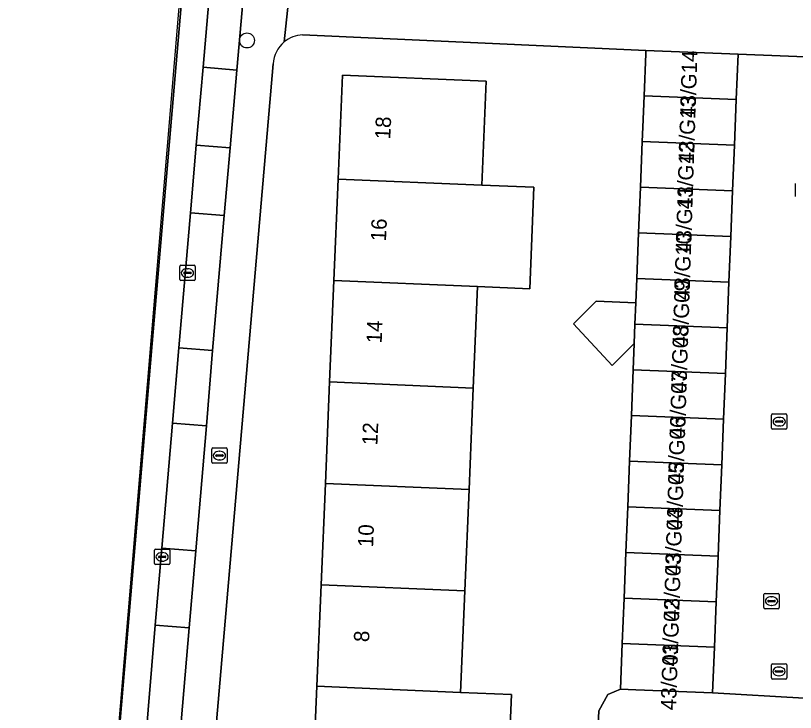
# Model space of a CAD drawing. Extents: x 161354 to 162026, y 386504 to 387460.
# Drawn here: x 161385.3 to 161436.1, y 386908.4 to 386953.7 of the extents above; entities that cross this region are included whole.
import ezdxf

# ---------------------------------------------------------------- set-up
doc = ezdxf.new("R2010")
doc.units = 0
for name, color, linetype in [('IMGEO_Boom', 7, 'Continuous'), ('IMGEO_Brandkraan', 7, 'Continuous'), ('IMGEO_Erf', 7, 'Continuous'), ('IMGEO_Kolk', 7, 'Continuous'), ('IMGEO_Pand', 7, 'Continuous'), ('IMGEO_Pand_nummerreeks', 7, 'Continuous'), ('IMGEO_Parkeervlak_open', 7, 'Continuous'), ('IMGEO_Rijbaan_lokaal_gesloten', 7, 'Continuous'), ('IMGEO_Rijbaan_lokaal_open', 7, 'Continuous'), ('IMGEO_Rioolput', 7, 'Continuous'), ('IMGEO_Voetpad_open', 7, 'Continuous')]:
    doc.layers.add(name, color=color, linetype=linetype)

msp = doc.modelspace()

# ---------------------------------------------------------------- linework, layer by layer
at = {"layer": 'IMGEO_Boom'}
msp.add_circle((161400.403, 386952.127), 0.489, dxfattribs=at)
at = {"layer": 'IMGEO_Brandkraan'}
for p, q in [((161398.112, 386924.666), (161398.112, 386925.518)), ((161398.187, 386925.592), (161399.039, 386925.592)), ((161399.113, 386925.518), (161399.113, 386924.666)), ((161398.371, 386925.086), (161398.371, 386925.098)), ((161398.809, 386925.049), (161398.411, 386925.049)), ((161398.414, 386925.135), (161398.812, 386925.135)), ((161398.6, 386925.372), (161398.625, 386925.372)), ((161398.855, 386925.098), (161398.855, 386925.086)), ((161399.039, 386924.592), (161398.187, 386924.592)), ((161398.623, 386924.812), (161398.598, 386924.812))]:
    msp.add_line(p, q, dxfattribs=at)
for points in [[(161398.112, 386924.666), (161398.112, 386925.518)], [(161398.187, 386925.592), (161399.039, 386925.592)], [(161399.113, 386925.518), (161399.113, 386924.666)], [(161399.039, 386924.592), (161398.187, 386924.592)]]:
    msp.add_lwpolyline(points, dxfattribs=at)
for centre, radius, start, end in [((161398.189, 386925.516), 0.0765, 91.552, 178.448), ((161398.189, 386925.516), 0.0765, 91.552, 178.448), ((161399.037, 386925.516), 0.0765, 1.552, 88.448), ((161399.037, 386925.516), 0.0765, 1.552, 88.448), ((161398.411, 386925.095), 0.0403, 85.8775, 175.7526), ((161398.408, 386925.085), 0.0366, 178.938, 274.7102), ((161398.812, 386925.092), 0.043, 264.8664, 352.4533), ((161398.816, 386925.097), 0.0386, 1.7309, 96.639), ((161398.189, 386924.668), 0.0765, 181.552, 268.448), ((161398.189, 386924.668), 0.0765, 181.552, 268.448), ((161399.037, 386924.668), 0.0765, 271.552, 358.448), ((161399.037, 386924.668), 0.0765, 271.552, 358.448)]:
    msp.add_arc(centre, radius, start, end, dxfattribs=at)
for centre, major_axis, ratio, start_param, end_param in [((161398.599, 386925.092), (-0.387, 0.002), 0.722429, 4.712389, 7.853982), ((161398.624, 386925.092), (-0.39, 0.002), 0.717154, 1.570796, 4.712389)]:
    msp.add_ellipse(centre, major_axis=major_axis, ratio=ratio, start_param=start_param, end_param=end_param, dxfattribs=at)
at = {"layer": 'IMGEO_Erf'}
for points in [[(161425.091, 386918.792), (161425.209, 386921.764), (161425.327, 386924.736), (161425.445, 386927.707), (161425.563, 386930.679), (161425.631, 386932.394), (161424.203, 386930.958), (161421.671, 386933.664), (161423.142, 386935.143), (161425.736, 386935.04), (161425.799, 386936.623), (161425.917, 386939.595), (161426.035, 386942.567), (161426.153, 386945.539), (161426.191, 386946.487), (161426.271, 386948.51), (161426.38, 386951.257), (161426.389, 386951.483), (161404.023, 386952.492)], [(161402.118, 386950.602), (161396.472, 386885.071)], [(161404.675, 386903.466), (161404.953, 386910.072), (161405.232, 386916.678), (161405.511, 386923.284), (161405.789, 386929.89), (161406.068, 386936.496), (161406.347, 386943.103), (161406.632, 386949.86), (161415.99, 386949.466), (161415.705, 386942.708), (161419.102, 386942.565), (161418.823, 386935.958), (161415.426, 386936.101), (161415.147, 386929.495), (161414.869, 386922.889), (161414.59, 386916.283), (161414.311, 386909.678), (161417.64, 386909.538), (161417.362, 386902.932)], [(161398.199, 386883.13), (161402.57, 386883.034), (161422.037, 386882.246), (161423.317, 386908.469), (161423.916, 386909.531), (161424.737, 386909.876), (161424.855, 386912.848), (161424.973, 386915.82), (161425.091, 386918.792)]]:
    msp.add_lwpolyline(points, dxfattribs=at)
for centre, radius, start, end in [((161404.098, 386950.507), 1.987, 92.1688, 129.8934), ((161404.096, 386950.514), 1.98, 129.9717, 177.4448)]:
    msp.add_arc(centre, radius, start, end, dxfattribs=at)
at = {"layer": 'IMGEO_Kolk'}
for p, q in [((161396.028, 386936.559), (161396.028, 386937.411)), ((161396.103, 386937.485), (161396.955, 386937.485)), ((161396.516, 386937.265), (161396.541, 386937.265)), ((161397.029, 386937.411), (161397.029, 386936.559)), ((161396.287, 386936.979), (161396.287, 386936.991)), ((161396.725, 386936.942), (161396.327, 386936.942)), ((161396.33, 386937.028), (161396.728, 386937.028)), ((161396.539, 386936.705), (161396.514, 386936.705)), ((161396.771, 386936.991), (161396.771, 386936.979)), ((161396.955, 386936.485), (161396.103, 386936.485)), ((161434.574, 386926.879), (161434.574, 386927.731)), ((161434.649, 386927.805), (161435.501, 386927.805)), ((161435.062, 386927.585), (161435.087, 386927.585)), ((161435.575, 386927.731), (161435.575, 386926.879)), ((161434.833, 386927.299), (161434.833, 386927.311)), ((161435.271, 386927.262), (161434.873, 386927.262)), ((161434.876, 386927.348), (161435.274, 386927.348)), ((161435.085, 386927.025), (161435.06, 386927.025)), ((161435.317, 386927.311), (161435.317, 386927.299)), ((161435.501, 386926.805), (161434.649, 386926.805)), ((161394.378, 386918.073), (161394.378, 386918.925)), ((161394.453, 386918.999), (161395.305, 386918.999)), ((161395.379, 386918.925), (161395.379, 386918.073)), ((161394.637, 386918.493), (161394.637, 386918.505)), ((161395.075, 386918.456), (161394.677, 386918.456)), ((161394.68, 386918.542), (161395.078, 386918.542)), ((161394.866, 386918.779), (161394.891, 386918.779)), ((161395.121, 386918.505), (161395.121, 386918.493)), ((161395.305, 386917.999), (161394.453, 386917.999)), ((161394.889, 386918.219), (161394.864, 386918.219)), ((161434.077, 386915.196), (161434.077, 386916.048)), ((161434.152, 386916.122), (161435.004, 386916.122)), ((161434.565, 386915.902), (161434.59, 386915.902)), ((161435.078, 386916.048), (161435.078, 386915.196)), ((161434.336, 386915.616), (161434.336, 386915.628)), ((161434.774, 386915.579), (161434.376, 386915.579)), ((161434.379, 386915.665), (161434.777, 386915.665)), ((161434.588, 386915.342), (161434.563, 386915.342)), ((161434.82, 386915.628), (161434.82, 386915.616)), ((161435.004, 386915.122), (161434.152, 386915.122))]:
    msp.add_line(p, q, dxfattribs=at)
for points in [[(161396.028, 386936.559), (161396.028, 386937.411)], [(161396.103, 386937.485), (161396.955, 386937.485)], [(161397.029, 386937.411), (161397.029, 386936.559)], [(161396.955, 386936.485), (161396.103, 386936.485)], [(161434.574, 386926.879), (161434.574, 386927.731)], [(161434.649, 386927.805), (161435.501, 386927.805)], [(161435.575, 386927.731), (161435.575, 386926.879)], [(161435.501, 386926.805), (161434.649, 386926.805)], [(161394.378, 386918.073), (161394.378, 386918.925)], [(161394.453, 386918.999), (161395.305, 386918.999)], [(161395.379, 386918.925), (161395.379, 386918.073)], [(161395.305, 386917.999), (161394.453, 386917.999)], [(161434.077, 386915.196), (161434.077, 386916.048)], [(161434.152, 386916.122), (161435.004, 386916.122)], [(161435.078, 386916.048), (161435.078, 386915.196)], [(161435.004, 386915.122), (161434.152, 386915.122)]]:
    msp.add_lwpolyline(points, dxfattribs=at)
for centre, radius, start, end in [((161396.105, 386937.409), 0.0765, 91.552, 178.448), ((161396.105, 386937.409), 0.0765, 91.552, 178.448), ((161396.953, 386937.409), 0.0765, 1.552, 88.448), ((161396.953, 386937.409), 0.0765, 1.552, 88.448), ((161396.327, 386936.988), 0.0403, 85.8775, 175.7526), ((161396.324, 386936.978), 0.0366, 178.938, 274.7102), ((161396.728, 386936.985), 0.043, 264.8664, 352.4533), ((161396.732, 386936.99), 0.0386, 1.7309, 96.639), ((161396.105, 386936.561), 0.0765, 181.552, 268.448), ((161396.105, 386936.561), 0.0765, 181.552, 268.448), ((161396.953, 386936.561), 0.0765, 271.552, 358.448), ((161396.953, 386936.561), 0.0765, 271.552, 358.448), ((161434.651, 386927.729), 0.0765, 91.552, 178.448), ((161434.651, 386927.729), 0.0765, 91.552, 178.448), ((161435.499, 386927.729), 0.0765, 1.552, 88.448), ((161435.499, 386927.729), 0.0765, 1.552, 88.448), ((161434.873, 386927.308), 0.0403, 85.8775, 175.7526), ((161434.87, 386927.298), 0.0366, 178.938, 274.7102), ((161435.274, 386927.305), 0.043, 264.8664, 352.4533), ((161435.278, 386927.31), 0.0386, 1.7309, 96.639), ((161434.651, 386926.881), 0.0765, 181.552, 268.448), ((161434.651, 386926.881), 0.0765, 181.552, 268.448), ((161435.499, 386926.881), 0.0765, 271.552, 358.448), ((161435.499, 386926.881), 0.0765, 271.552, 358.448), ((161394.455, 386918.923), 0.0765, 91.552, 178.448), ((161394.455, 386918.923), 0.0765, 91.552, 178.448), ((161395.303, 386918.923), 0.0765, 1.552, 88.448), ((161395.303, 386918.923), 0.0765, 1.552, 88.448), ((161394.677, 386918.502), 0.0403, 85.8775, 175.7526), ((161394.674, 386918.492), 0.0366, 178.938, 274.7102), ((161395.078, 386918.499), 0.043, 264.8664, 352.4533), ((161395.082, 386918.504), 0.0386, 1.7309, 96.639), ((161394.455, 386918.075), 0.0765, 181.552, 268.448), ((161394.455, 386918.075), 0.0765, 181.552, 268.448), ((161395.303, 386918.075), 0.0765, 271.552, 358.448), ((161395.303, 386918.075), 0.0765, 271.552, 358.448), ((161434.154, 386916.046), 0.0765, 91.552, 178.448), ((161434.154, 386916.046), 0.0765, 91.552, 178.448), ((161435.002, 386916.046), 0.0765, 1.552, 88.448), ((161435.002, 386916.046), 0.0765, 1.552, 88.448), ((161434.376, 386915.625), 0.0403, 85.8775, 175.7526), ((161434.373, 386915.615), 0.0366, 178.938, 274.7102), ((161434.777, 386915.622), 0.043, 264.8664, 352.4533), ((161434.781, 386915.627), 0.0386, 1.7309, 96.639), ((161434.154, 386915.198), 0.0765, 181.552, 268.448), ((161434.154, 386915.198), 0.0765, 181.552, 268.448), ((161435.002, 386915.198), 0.0765, 271.552, 358.448), ((161435.002, 386915.198), 0.0765, 271.552, 358.448)]:
    msp.add_arc(centre, radius, start, end, dxfattribs=at)
for centre, major_axis, ratio, start_param, end_param in [((161396.515, 386936.985), (-0.387, 0.002), 0.722429, 4.712389, 7.853982), ((161396.54, 386936.985), (-0.39, 0.002), 0.717154, 1.570796, 4.712389), ((161435.061, 386927.305), (-0.387, 0.002), 0.722429, 4.712389, 7.853982), ((161435.086, 386927.305), (-0.39, 0.002), 0.717154, 1.570796, 4.712389), ((161394.865, 386918.499), (-0.387, 0.002), 0.722429, 4.712389, 7.853982), ((161394.89, 386918.499), (-0.39, 0.002), 0.717154, 1.570796, 4.712389), ((161434.564, 386915.622), (-0.387, 0.002), 0.722429, 4.712389, 7.853982), ((161434.589, 386915.622), (-0.39, 0.002), 0.717154, 1.570796, 4.712389)]:
    msp.add_ellipse(centre, major_axis=major_axis, ratio=ratio, start_param=start_param, end_param=end_param, dxfattribs=at)
at = {"layer": 'IMGEO_Pand'}
for points in [[(161432.392, 386951.244), (161426.389, 386951.483), (161426.38, 386951.257), (161426.271, 386948.51), (161432.274, 386948.272)], [(161415.705, 386942.708), (161415.99, 386949.466), (161406.632, 386949.86), (161406.347, 386943.103)], [(161432.274, 386948.272), (161426.271, 386948.51), (161426.191, 386946.487), (161426.153, 386945.539), (161432.156, 386945.3)], [(161432.156, 386945.3), (161426.153, 386945.539), (161426.035, 386942.567), (161432.038, 386942.328)], [(161418.823, 386935.958), (161419.102, 386942.565), (161415.705, 386942.708), (161406.347, 386943.103), (161406.068, 386936.496), (161415.426, 386936.101)], [(161432.038, 386942.328), (161426.035, 386942.567), (161425.917, 386939.595), (161431.92, 386939.357)], [(161431.92, 386939.357), (161425.917, 386939.595), (161425.799, 386936.623), (161431.802, 386936.385)], [(161415.147, 386929.495), (161415.426, 386936.101), (161406.068, 386936.496), (161405.789, 386929.89)], [(161431.802, 386936.385), (161425.799, 386936.623), (161425.736, 386935.04), (161425.681, 386933.651), (161431.684, 386933.413)], [(161425.681, 386933.651), (161425.736, 386935.04), (161423.142, 386935.143), (161421.671, 386933.664), (161424.203, 386930.958), (161425.631, 386932.394)], [(161431.684, 386933.413), (161425.681, 386933.651), (161425.631, 386932.394), (161425.563, 386930.679), (161431.566, 386930.441)], [(161431.566, 386930.441), (161425.563, 386930.679), (161425.445, 386927.707), (161431.448, 386927.469)], [(161414.869, 386922.889), (161415.147, 386929.495), (161405.789, 386929.89), (161405.511, 386923.284)], [(161431.448, 386927.469), (161425.445, 386927.707), (161425.327, 386924.736), (161431.33, 386924.497)], [(161431.33, 386924.497), (161425.327, 386924.736), (161425.209, 386921.764), (161431.212, 386921.525)], [(161405.511, 386923.284), (161405.232, 386916.678), (161414.59, 386916.283), (161414.869, 386922.889)], [(161431.212, 386921.525), (161425.209, 386921.764), (161425.091, 386918.792), (161431.094, 386918.554)], [(161431.094, 386918.554), (161425.091, 386918.792), (161424.973, 386915.82), (161430.976, 386915.582)], [(161414.311, 386909.678), (161414.59, 386916.283), (161405.232, 386916.678), (161404.953, 386910.072)], [(161430.976, 386915.582), (161424.973, 386915.82), (161424.855, 386912.848), (161430.858, 386912.61)], [(161430.858, 386912.61), (161424.855, 386912.848), (161424.737, 386909.876), (161425.744, 386909.836), (161430.74, 386909.638)], [(161414.311, 386909.678), (161404.953, 386910.072), (161404.675, 386903.466), (161414.033, 386903.072), (161417.362, 386902.932), (161417.64, 386909.538)]]:
    msp.add_lwpolyline(points, close=True, dxfattribs=at)
at = {"layer": 'IMGEO_Parkeervlak_open'}
for points in [[(161401.052, 386964.949), (161398.813, 386965.051), (161397.56, 386950.381), (161399.743, 386950.199)], [(161399.306, 386945.132), (161397.098, 386945.3), (161396.726, 386940.898), (161398.926, 386940.724)], [(161398.169, 386931.948), (161395.968, 386932.108), (161395.562, 386927.216), (161397.759, 386927.033)], [(161397.063, 386918.895), (161394.863, 386919.073), (161394.434, 386914.054), (161396.638, 386913.88)]]:
    msp.add_lwpolyline(points, close=True, dxfattribs=at)
at = {"layer": 'IMGEO_Rijbaan_lokaal_gesloten'}
for points in [[(161407.469, 387085.902), (161407.502, 387088.315), (161407.694, 387090.665), (161407.844, 387092.692), (161407.62, 387092.708), (161403.029, 387038.37), (161389.859, 386881.623), (161385.332, 386827.741)], [(161406.674, 387079.565), (161402.616, 387030.052), (161394.233, 386932.401), (161389.344, 386874.852), (161388.763, 386863.237), (161388.746, 386863.053), (161388.119, 386839.423)], [(161388.119, 386839.423), (161388.746, 386863.053), (161388.763, 386863.237), (161389.344, 386874.852), (161394.233, 386932.401), (161402.616, 387030.052), (161406.674, 387079.565)], [(161393.289, 386900.719), (161393.743, 386905.917), (161394.434, 386914.054), (161394.863, 386919.073), (161395.562, 386927.216), (161395.968, 386932.108), (161396.726, 386940.898), (161397.098, 386945.3), (161397.56, 386950.381), (161398.813, 386965.051), (161399.546, 386973.261), (161399.972, 386978.208), (161400.667, 386986.316), (161401.089, 386991.236), (161401.793, 386999.383), (161402.199, 387004.388), (161402.917, 387012.858), (161403.316, 387017.566), (161403.709, 387022.054)]]:
    msp.add_lwpolyline(points, dxfattribs=at)
at = {"layer": 'IMGEO_Rijbaan_lokaal_open'}
msp.add_lwpolyline([(161441.686, 386950.859), (161432.392, 386951.244), (161432.274, 386948.272), (161432.156, 386945.3), (161432.038, 386942.328), (161431.92, 386939.357), (161431.802, 386936.385), (161431.684, 386933.413), (161431.566, 386930.441), (161431.448, 386927.469), (161431.33, 386924.497), (161431.212, 386921.525), (161431.094, 386918.554), (161430.976, 386915.582), (161430.858, 386912.61), (161430.74, 386909.638), (161436.696, 386909.288)], dxfattribs=at)
for points in [[(161399.743, 386950.199), (161397.56, 386950.381), (161397.098, 386945.3), (161399.306, 386945.132)], [(161398.926, 386940.724), (161396.726, 386940.898), (161395.968, 386932.108), (161398.169, 386931.948)], [(161397.759, 386927.033), (161395.562, 386927.216), (161394.863, 386919.073), (161397.063, 386918.895)], [(161396.638, 386913.88), (161394.434, 386914.054), (161393.743, 386905.917), (161395.938, 386905.726)]]:
    msp.add_lwpolyline(points, close=True, dxfattribs=at)
at = {"layer": 'IMGEO_Rioolput'}
for p, q in [((161436.13, 386941.957), (161436.13, 386942.809)), ((161434.563, 386910.616), (161434.563, 386911.468)), ((161434.638, 386911.542), (161435.49, 386911.542)), ((161435.051, 386911.322), (161435.076, 386911.322)), ((161435.564, 386911.468), (161435.564, 386910.616)), ((161434.822, 386911.036), (161434.822, 386911.048)), ((161435.26, 386910.999), (161434.862, 386910.999)), ((161434.865, 386911.085), (161435.263, 386911.085)), ((161435.074, 386910.762), (161435.049, 386910.762)), ((161435.306, 386911.048), (161435.306, 386911.036)), ((161435.49, 386910.542), (161434.638, 386910.542))]:
    msp.add_line(p, q, dxfattribs=at)
for points in [[(161436.13, 386941.957), (161436.13, 386942.809)], [(161434.563, 386910.616), (161434.563, 386911.468)], [(161434.638, 386911.542), (161435.49, 386911.542)], [(161435.564, 386911.468), (161435.564, 386910.616)], [(161435.49, 386910.542), (161434.638, 386910.542)]]:
    msp.add_lwpolyline(points, dxfattribs=at)
for centre, radius, start, end in [((161434.64, 386911.466), 0.0765, 91.552, 178.448), ((161434.64, 386911.466), 0.0765, 91.552, 178.448), ((161435.488, 386911.466), 0.0765, 1.552, 88.448), ((161435.488, 386911.466), 0.0765, 1.552, 88.448), ((161434.862, 386911.045), 0.0403, 85.8775, 175.7526), ((161434.859, 386911.035), 0.0366, 178.938, 274.7102), ((161435.263, 386911.042), 0.043, 264.8664, 352.4533), ((161435.267, 386911.047), 0.0386, 1.7309, 96.639), ((161434.64, 386910.618), 0.0765, 181.552, 268.448), ((161434.64, 386910.618), 0.0765, 181.552, 268.448), ((161435.488, 386910.618), 0.0765, 271.552, 358.448), ((161435.488, 386910.618), 0.0765, 271.552, 358.448)]:
    msp.add_arc(centre, radius, start, end, dxfattribs=at)
for centre, major_axis, ratio, start_param, end_param in [((161435.05, 386911.042), (-0.387, 0.002), 0.722429, 4.712389, 7.853982), ((161435.075, 386911.042), (-0.39, 0.002), 0.717154, 1.570796, 4.712389)]:
    msp.add_ellipse(centre, major_axis=major_axis, ratio=ratio, start_param=start_param, end_param=end_param, dxfattribs=at)
at = {"layer": 'IMGEO_Voetpad_open'}
for points in [[(161406.704, 387031.106), (161405.921, 387021.886), (161405.516, 387017.383), (161405.133, 387012.676), (161404.391, 387004.207), (161403.992, 386999.21), (161403.265, 386991.063), (161402.872, 386986.156), (161402.159, 386978.009), (161401.738, 386973.087), (161401.052, 386964.949), (161399.743, 386950.199), (161399.306, 386945.132), (161398.926, 386940.724), (161398.169, 386931.948), (161397.759, 386927.033), (161397.063, 386918.895), (161396.638, 386913.88), (161395.938, 386905.726), (161395.517, 386900.935), (161393.823, 386901.064)], [(161403.227, 386955.728), (161402.824, 386952.031)], [(161402.824, 386952.031), (161403.227, 386955.728)], [(161404.023, 386952.492), (161426.389, 386951.483), (161432.392, 386951.244), (161441.686, 386950.859), (161468.19, 386949.762)], [(161396.472, 386885.071), (161402.118, 386950.602)], [(161436.696, 386909.288), (161430.74, 386909.638), (161425.744, 386909.836), (161424.737, 386909.876), (161423.916, 386909.531), (161423.317, 386908.469), (161422.037, 386882.246)]]:
    msp.add_lwpolyline(points, dxfattribs=at)
for centre, radius, start, end in [((161404.098, 386950.507), 1.987, 92.1688, 129.8934), ((161404.096, 386950.514), 1.98, 129.9717, 177.4448)]:
    msp.add_arc(centre, radius, start, end, dxfattribs=at)

# ---------------------------------------------------------------- texts
at = {"layer": 'IMGEO_Pand_nummerreeks'}
for s, rotation, p in [('43/G14', 88.1339, (161429.611, 386947.073)), ('43/G13', 88.1339, (161429.514, 386944.105)), ('18', 87.5842, (161409.738, 386945.671)), ('43/G12', 88.1339, (161429.417, 386941.13)), ('43/G11', 88.1339, (161429.324, 386938.277)), ('16', 87.5842, (161409.458, 386939.029)), ('43/G10', 88.1339, (161429.224, 386935.202)), ('43/G09', 88.1324, (161429.124, 386932.135)), ('14', 87.5842, (161409.178, 386932.389)), ('43/G08', 88.1324, (161429.027, 386929.173)), ('43/G07', 88.1339, (161428.931, 386926.201)), ('43/G06', 88.1339, (161428.834, 386923.232)), ('12', 87.5842, (161408.898, 386925.747)), ('43/G05', 88.1339, (161428.737, 386920.263)), ('43/G04', 88.1339, (161428.64, 386917.295)), ('10', 87.5842, (161408.618, 386919.113)), ('43/G03', 88.1339, (161428.544, 386914.326)), ('43/G02', 88.1339, (161428.447, 386911.351)), ('8', 87.5842, (161408.357, 386912.934)), ('43/G01', 88.1339, (161428.354, 386908.499))]:
    msp.add_text(s, height=1, rotation=rotation, dxfattribs=at).set_placement(p)

doc.saveas('drawing.dxf')
